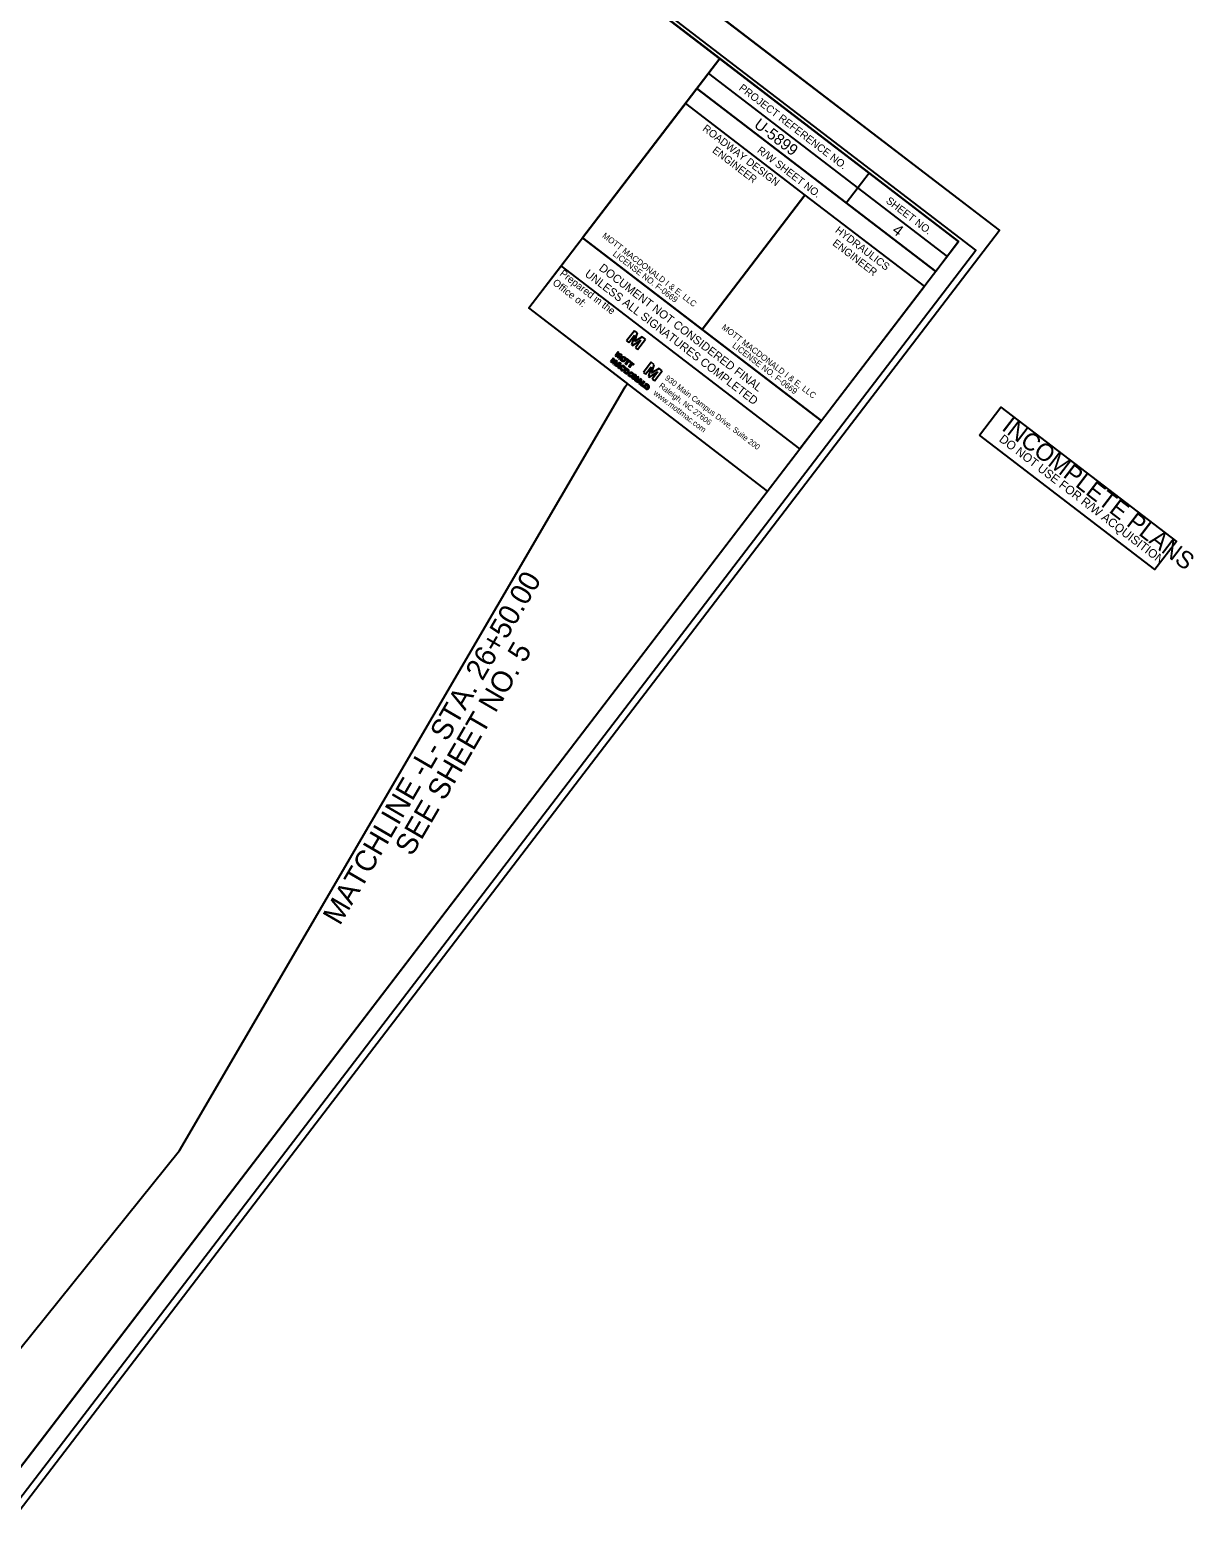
# Model space of a CAD drawing. Extents: x 1617779 to 1619910, y 897617 to 899510.
# Drawn here: x 1619136 to 1619910, y 897617 to 898620 of the extents above; entities that cross this region are included whole.
import ezdxf

# ---------------------------------------------------------------- set-up
doc = ezdxf.new("R2010")
doc.units = 0
for name, color, linetype in [('Matchline', 7, 'Continuous'), ('Matchline Text', 7, 'Continuous'), ('Old_Level_2', 7, 'Continuous'), ('Old_Level_42', 7, 'Continuous'), ('Old_Level_45', 7, 'Continuous'), ('Sheet Cutting Line CELL', 7, 'Continuous'), ('Sheet Data Field CELL', 7, 'Continuous'), ('Sheet Layout Plan Border', 7, 'Continuous'), ('Sheet Plan CELL', 7, 'Continuous'), ('Sheet Plot Border Inside CELL', 7, 'Continuous'), ('Sheet Plot Border Outside CELL', 7, 'Continuous'), ('Sheet Sticker Exception Certification CELL', 7, 'Continuous'), ('Sheet Sticker Incomplete CELL', 7, 'Continuous')]:
    doc.layers.add(name, color=color, linetype=linetype)

msp = doc.modelspace()

# ---------------------------------------------------------------- linework, layer by layer
at = {"layer": 'Matchline'}
msp.add_line((1619235.7, 897874.9), (1619531.9, 898382.6), dxfattribs=at)
at = {"layer": 'Old_Level_2'}
for p, q in [((1619538.1, 898419.9), (1619532.9, 898413.1)), ((1619534.4, 898412), (1619538.1, 898416.9)), ((1619538.1, 898416.9), (1619536.3, 898410.6)), ((1619540.1, 898418.4), (1619538.1, 898419.9)), ((1619538.1, 898416.9), (1619538.1, 898416.9)), ((1619538.5, 898412.9), (1619540.1, 898418.4)), ((1619543.4, 898415.8), (1619538.6, 898412.9)), ((1619545.4, 898414.3), (1619543.4, 898415.8)), ((1619527.3, 898405.8), (1619525.3, 898403.2)), ((1619528, 898405.2), (1619527.3, 898405.8)), ((1619527.4, 898403.1), (1619528, 898405.2)), ((1619532.9, 898413.1), (1619534.4, 898412)), ((1619536.3, 898410.6), (1619536.9, 898410.1)), ((1619536.9, 898410.1), (1619542.5, 898413.5)), ((1619538.6, 898412.9), (1619538.5, 898412.8)), ((1619538.5, 898412.8), (1619538.5, 898412.9)), ((1619538.5, 898412.9), (1619538.5, 898412.9)), ((1619542.5, 898413.5), (1619538.8, 898408.6)), ((1619538.8, 898408.6), (1619540.2, 898407.5)), ((1619540.2, 898407.5), (1619545.4, 898414.3)), ((1619542.5, 898413.5), (1619542.5, 898413.5)), ((1619524.2, 898401.7), (1619522.2, 898399.2)), ((1619522.2, 898399.2), (1619522.8, 898398.8)), ((1619522.8, 898398.8), (1619524.2, 898400.6)), ((1619524.2, 898400.6), (1619523.5, 898398.2)), ((1619523.5, 898398.2), (1619523.8, 898398)), ((1619523.8, 898398), (1619525.9, 898399.3)), ((1619525, 898401.2), (1619524.2, 898401.7)), ((1619524.2, 898400.6), (1619524.2, 898400.6)), ((1619524.4, 898399.1), (1619525, 898401.2)), ((1619526.2, 898400.2), (1619524.4, 898399.1)), ((1619525.9, 898399.3), (1619524.5, 898397.4)), ((1619524.5, 898397.4), (1619525, 898397)), ((1619525, 898397), (1619527, 898399.6)), ((1619525.3, 898403.2), (1619525.8, 898402.8)), ((1619525.8, 898402.8), (1619527.3, 898404.6)), ((1619525.9, 898399.3), (1619525.9, 898399.3)), ((1619527, 898399.6), (1619526.2, 898400.2)), ((1619527.3, 898404.6), (1619526.6, 898402.2)), ((1619526.6, 898402.2), (1619526.8, 898402)), ((1619526.8, 898402), (1619529, 898403.3)), ((1619527.3, 898404.6), (1619527.3, 898404.6)), ((1619527.3, 898404.6), (1619527.3, 898404.6)), ((1619529.3, 898404.2), (1619527.4, 898403.1)), ((1619529, 898403.3), (1619527.6, 898401.4)), ((1619527.6, 898401.4), (1619528.1, 898401)), ((1619528.1, 898401), (1619530.1, 898403.6)), ((1619529, 898403.3), (1619529, 898403.3)), ((1619529, 898403.3), (1619529, 898403.3)), ((1619529, 898403.3), (1619529, 898403.3)), ((1619530.1, 898403.6), (1619529.3, 898404.2)), ((1619532.8, 898395.1), (1619531.8, 898393.8)), ((1619534, 898394.2), (1619532.8, 898395.1)), ((1619549.2, 898398.9), (1619544.1, 898392.1)), ((1619545.5, 898391), (1619549.2, 898395.9)), ((1619549.2, 898395.9), (1619547.4, 898389.6)), ((1619551.2, 898397.3), (1619549.2, 898398.9)), ((1619549.2, 898395.9), (1619549.2, 898395.9)), ((1619549.7, 898391.9), (1619551.2, 898397.3)), ((1619530.9, 898393.4), (1619530.6, 898394)), ((1619531.8, 898393.8), (1619530.9, 898392.5)), ((1619530.9, 898392.5), (1619532.1, 898391.6)), ((1619531.4, 898394.9), (1619532, 898394.8)), ((1619531.8, 898392.6), (1619533, 898394.2)), ((1619532.4, 898392.1), (1619531.8, 898392.6)), ((1619533, 898394.2), (1619533.7, 898393.7)), ((1619544.1, 898392.1), (1619545.5, 898391)), ((1619547.4, 898389.6), (1619548, 898389.1)), ((1619548, 898389.1), (1619553.7, 898392.5)), ((1619549.7, 898391.8), (1619549.6, 898391.9)), ((1619549.6, 898391.9), (1619549.7, 898391.9)), ((1619554.5, 898394.8), (1619549.7, 898391.9)), ((1619549.7, 898391.9), (1619549.7, 898391.8)), ((1619553.7, 898392.5), (1619549.9, 898387.6)), ((1619549.9, 898387.6), (1619551.4, 898386.5)), ((1619551.4, 898386.5), (1619556.5, 898393.3)), ((1619553.7, 898392.5), (1619553.7, 898392.5)), ((1619556.5, 898393.3), (1619554.5, 898394.8)), ((1619545.2, 898383.6), (1619544.2, 898382.3)), ((1619544.2, 898382.3), (1619545.4, 898381.4)), ((1619545.1, 898382.4), (1619546.4, 898384)), ((1619545.8, 898381.9), (1619545.1, 898382.4)), ((1619546.2, 898384.9), (1619545.2, 898383.6)), ((1619546.2, 898384.9), (1619546.2, 898384.9)), ((1619547.4, 898384), (1619546.2, 898384.9)), ((1619546.4, 898384), (1619547, 898383.5)), ((1619547, 898383.5), (1619547, 898383.5))]:
    msp.add_line(p, q, dxfattribs=at)
for points in [[(1619525.3, 898396.8), (1619526, 898396.3), (1619526.5, 898396.6), (1619527.6, 898395.8), (1619527.4, 898395.2), (1619528, 898394.7), (1619529, 898398.1), (1619528.3, 898398.6), (1619525.3, 898396.8)], [(1619527, 898397), (1619528.2, 898397.8), (1619527.8, 898396.3), (1619527, 898397)], [(1619533, 898400.6), (1619533.7, 898400.1), (1619532.1, 898398), (1619532.6, 898397.5), (1619534.3, 898399.6), (1619535, 898399.1), (1619535.4, 898399.6), (1619533.3, 898401.1), (1619533, 898400.6)], [(1619535.3, 898398.8), (1619536.1, 898398.3), (1619534.5, 898396.2), (1619535, 898395.7), (1619536.6, 898397.8), (1619537.4, 898397.3), (1619537.7, 898397.7), (1619535.7, 898399.3), (1619535.3, 898398.8)], [(1619538.5, 898389.4), (1619538.5, 898389.4), (1619538.4, 898386.7), (1619539, 898386.3), (1619540.9, 898388.9), (1619540.4, 898389.3), (1619539.2, 898387.7), (1619539.2, 898390.3), (1619538.6, 898390.7), (1619536.7, 898388.1), (1619537.2, 898387.7), (1619538.5, 898389.4)], [(1619539.3, 898386.1), (1619539.9, 898385.6), (1619540.4, 898385.9), (1619541.5, 898385.1), (1619541.4, 898384.5), (1619542, 898384.1), (1619542.9, 898387.4), (1619542.3, 898387.9), (1619539.3, 898386.1)], [(1619540.9, 898386.3), (1619542.2, 898387.1), (1619541.7, 898385.7), (1619540.9, 898386.3)], [(1619543.9, 898382.6), (1619544.3, 898383), (1619543.2, 898383.9), (1619544.8, 898386), (1619544.2, 898386.4), (1619542.3, 898383.8), (1619543.9, 898382.6)]]:
    msp.add_lwpolyline(points, dxfattribs=at)
msp.add_arc((1619546.4, 898382.7), 1.62, 232.554, 52.554, dxfattribs=at)
for centre, major_axis, ratio, start_param, end_param in [((1619530.4, 898395), (0.99, 1.29), 0.993118, 5.246647, 10.366427), ((1619530.4, 898395), (0.644, 0.839), 0.916103, 5.276876, 10.296021), ((1619533, 898392.9), (-0.99, -1.29), 0.930276, 0, 3.141593), ((1619533, 898392.9), (-0.616, -0.805), 0.900832, 0, 3.141593), ((1619546.4, 898382.7), (-0.616, -0.805), 0.900832, 0, 3.141593)]:
    msp.add_ellipse(centre, major_axis=major_axis, ratio=ratio, start_param=start_param, end_param=end_param, dxfattribs=at)
for centre, major_axis, ratio in [((1619530.8, 898401), (0.99, 1.29), 0.993118), ((1619530.8, 898401), (0.644, 0.839), 0.916103), ((1619535.9, 898390.7), (0.99, 1.29), 0.993118), ((1619535.9, 898390.7), (0.644, 0.839), 0.916103)]:
    msp.add_ellipse(centre, major_axis=major_axis, ratio=ratio, dxfattribs=at)
at = {"layer": 'Old_Level_42'}
msp.add_lwpolyline([(1619626.7, 898313.3), (1619467.9, 898435), (1619489.4, 898463)], dxfattribs=at)
at = {"layer": 'Sheet Cutting Line CELL'}
msp.add_line((1619780.9, 898486.7), (1618444.3, 899510.3), dxfattribs=at)
at = {"layer": 'Sheet Layout Plan Border'}
msp.add_lwpolyline([(1618591.6, 899144.6), (1618571.1, 899153.2), (1618079.6, 898438.7), (1619075.6, 897675.9), (1619235.7, 897874.9), (1619531.9, 898382.6), (1619533.5, 898384.8), (1619467.9, 898435), (1619594.9, 898600.8), (1618667.3, 899311.1)], close=True, dxfattribs=at)
at = {"layer": 'Sheet Plan CELL'}
for p, q in [((1619587.3, 898590.8), (1619746.1, 898469.2)), ((1619579.6, 898580.9), (1619572.1, 898571)), ((1619579.6, 898580.9), (1619738.5, 898459.3)), ((1619694.1, 898524.7), (1619678.9, 898504.8)), ((1619651.5, 898510.1), (1619583.1, 898420.8))]:
    msp.add_line(p, q, dxfattribs=at)
for points in [[(1619753.7, 898479.1), (1618562.8, 899391.2), (1617924.4, 898557.6), (1619115.3, 897645.5)], [(1617924.4, 898557.6), (1618562.8, 899391.2), (1619594.9, 898600.8), (1619503.7, 898481.6), (1619662.5, 898360), (1619115.3, 897645.5)], [(1619594.9, 898600.8), (1619753.7, 898479.1), (1619738.5, 898459.3), (1619579.6, 898580.9)], [(1619572.1, 898571), (1619651.5, 898510.1), (1619583.1, 898420.8), (1619503.7, 898481.6)], [(1619651.5, 898510.1), (1619730.9, 898449.3), (1619662.5, 898360), (1619583.1, 898420.8)]]:
    msp.add_lwpolyline(points, close=True, dxfattribs=at)
at = {"layer": 'Sheet Plot Border Inside CELL'}
msp.add_lwpolyline([(1617801, 898648.9), (1619123.7, 897636), (1619765.2, 898473.5), (1618442.5, 899486.5)], close=True, dxfattribs=at)
at = {"layer": 'Sheet Plot Border Outside CELL'}
msp.add_lwpolyline([(1617778.5, 898640.9), (1619115.1, 897617.3), (1619780.9, 898486.7), (1618444.3, 899510.3)], close=True, dxfattribs=at)
at = {"layer": 'Sheet Sticker Exception Certification CELL'}
for p, q in [((1619489.4, 898463), (1619503.7, 898481.6)), ((1619503.7, 898481.6), (1619662.5, 898360)), ((1619648.2, 898341.4), (1619489.4, 898463)), ((1619662.5, 898360), (1619648.2, 898341.4))]:
    msp.add_line(p, q, dxfattribs=at)
at = {"layer": 'Sheet Sticker Incomplete CELL'}
msp.add_lwpolyline([(1619767.5, 898350.4), (1619781.8, 898369.1), (1619898.5, 898279.7), (1619884.2, 898261.1)], close=True, dxfattribs=at)

# ---------------------------------------------------------------- texts
at = {"layer": 'Matchline Text'}
for s, p in [('MATCHLINE -L- STA. 26+50.00', (1619342.3, 898023.9)), ('SEE SHEET NO. 5', (1619390.2, 898069.9))]:
    msp.add_text(s, height=14, rotation=59.769, dxfattribs=at).set_placement(p)
at = {"layer": 'Old_Level_2'}
for s, height, p in [('Prepared in the ', 4.819, (1619488.1, 898457.1)), ('Office of:', 4.82, (1619483.3, 898450.9)), ('Raleigh, NC 27606', 3.75, (1619554.1, 898382.6)), ('930 Main Campus Drive, Suite 200', 3.75, (1619558.1, 898387.7)), ('www.mottmac.com', 3.75, (1619550.4, 898377.7))]:
    msp.add_text(s, height=height, rotation=322.554, dxfattribs=at).set_placement(p)
at = {"layer": 'Old_Level_45'}
for s, p in [('MOTT MACDONALD I & E, LLC', (1619516.4, 898482.3)), (' LICENSE NO. F-0669', (1619522.2, 898471.1)), ('MOTT MACDONALD I & E, LLC', (1619595.8, 898421.4)), (' LICENSE NO. F-0669', (1619601.6, 898410.2))]:
    msp.add_text(s, height=4.018, rotation=322.554, dxfattribs=at).set_placement(p)
at = {"layer": 'Sheet Data Field CELL'}
for s, p in [('U-5899', (1619617.1, 898555.7)), ('4', (1619708.9, 898485.5))]:
    msp.add_text(s, height=7.5, rotation=322.554, dxfattribs=at).set_placement(p)
at = {"layer": 'Sheet Plan CELL'}
for s, p in [('PROJECT REFERENCE NO.', (1619607.2, 898580.4)), ('ROADWAY DESIGN', (1619583, 898553.4)), ('ENGINEER', (1619589.5, 898538.9)), ('R/W SHEET NO.', (1619619.3, 898538.9)), ('SHEET NO.', (1619704.9, 898505.4)), ('HYDRAULICS', (1619671.2, 898485.8)), ('ENGINEER', (1619669.4, 898477.2))]:
    msp.add_text(s, height=5, rotation=322.554, dxfattribs=at).set_placement(p)
at = {"layer": 'Sheet Sticker Exception Certification CELL'}
for s, p in [('UNLESS ALL SIGNATURES COMPLETED', (1619504.7, 898456.7)), ('DOCUMENT NOT CONSIDERED FINAL', (1619514.1, 898460.6))]:
    msp.add_text(s, height=5.5, rotation=322.554, dxfattribs=at).set_placement(p)
at = {"layer": 'Sheet Sticker Incomplete CELL'}
for s, height, p in [('INCOMPLETE PLANS', 11.52, (1619781.7, 898354.3)), ('DO NOT USE FOR R/W ACQUISITION', 5.76, (1619780.1, 898346.8))]:
    msp.add_text(s, height=height, rotation=322.554, dxfattribs=at).set_placement(p)

doc.saveas('drawing.dxf')
